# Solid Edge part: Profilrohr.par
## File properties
Username: bmolnar
Dokumentum tartalom típus: 0
Author: bmolnar
Last saved by: bmolnar
Revision: 85
Sűrűség: 0,000 kg/m^3
Pontosság: 0,990
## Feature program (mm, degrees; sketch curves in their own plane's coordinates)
base feature "unnamed BaseFeature 1"
thread "unnamed Thread 1"
thread "Menet_2"  ThreadDepth = 9.3 mm
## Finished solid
Body 1: solid body, 177 faces, 454 edges, 298 vertices.
  Faces by surface: plane 102, cylinder 65, cone 6, torus 4
  Edges by curve: line 308, circle 136, curve on surface 7, spline 2, intersection 1
Bounding box of the edges (mm; curved faces can reach further): 124.000 x 131.000 x 136.000, from (-62, -62, 0) to (62, 69, 136).
Cylindrical faces by radius (mm): R0.2 x24, R2.625 x2, R5.5 x8, R5.7225 x4, R8.6 x16, R50 x1, R50.85 x2, R51.1 x2, R53.1 x2, R84 x4
Conical faces (half-angle, radius in mm at the cone's reference point): 30 deg R50.325 x2, 30 deg R51.283 x2, 45 deg R6.0725 x2
Toroidal faces (ring radius, tube radius in mm): R52.9 r0.2 x4
Planar faces by outward normal: +x 9, +y 11, +z 8, -x 9, -y 9, -z 8, oblique 48
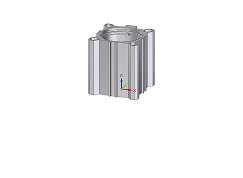
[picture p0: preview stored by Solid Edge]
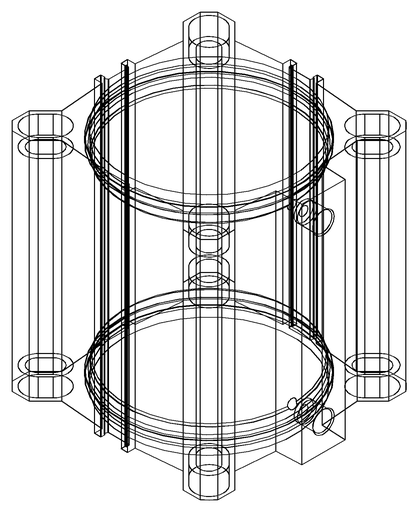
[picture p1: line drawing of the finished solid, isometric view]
